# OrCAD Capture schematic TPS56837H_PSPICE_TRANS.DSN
size C
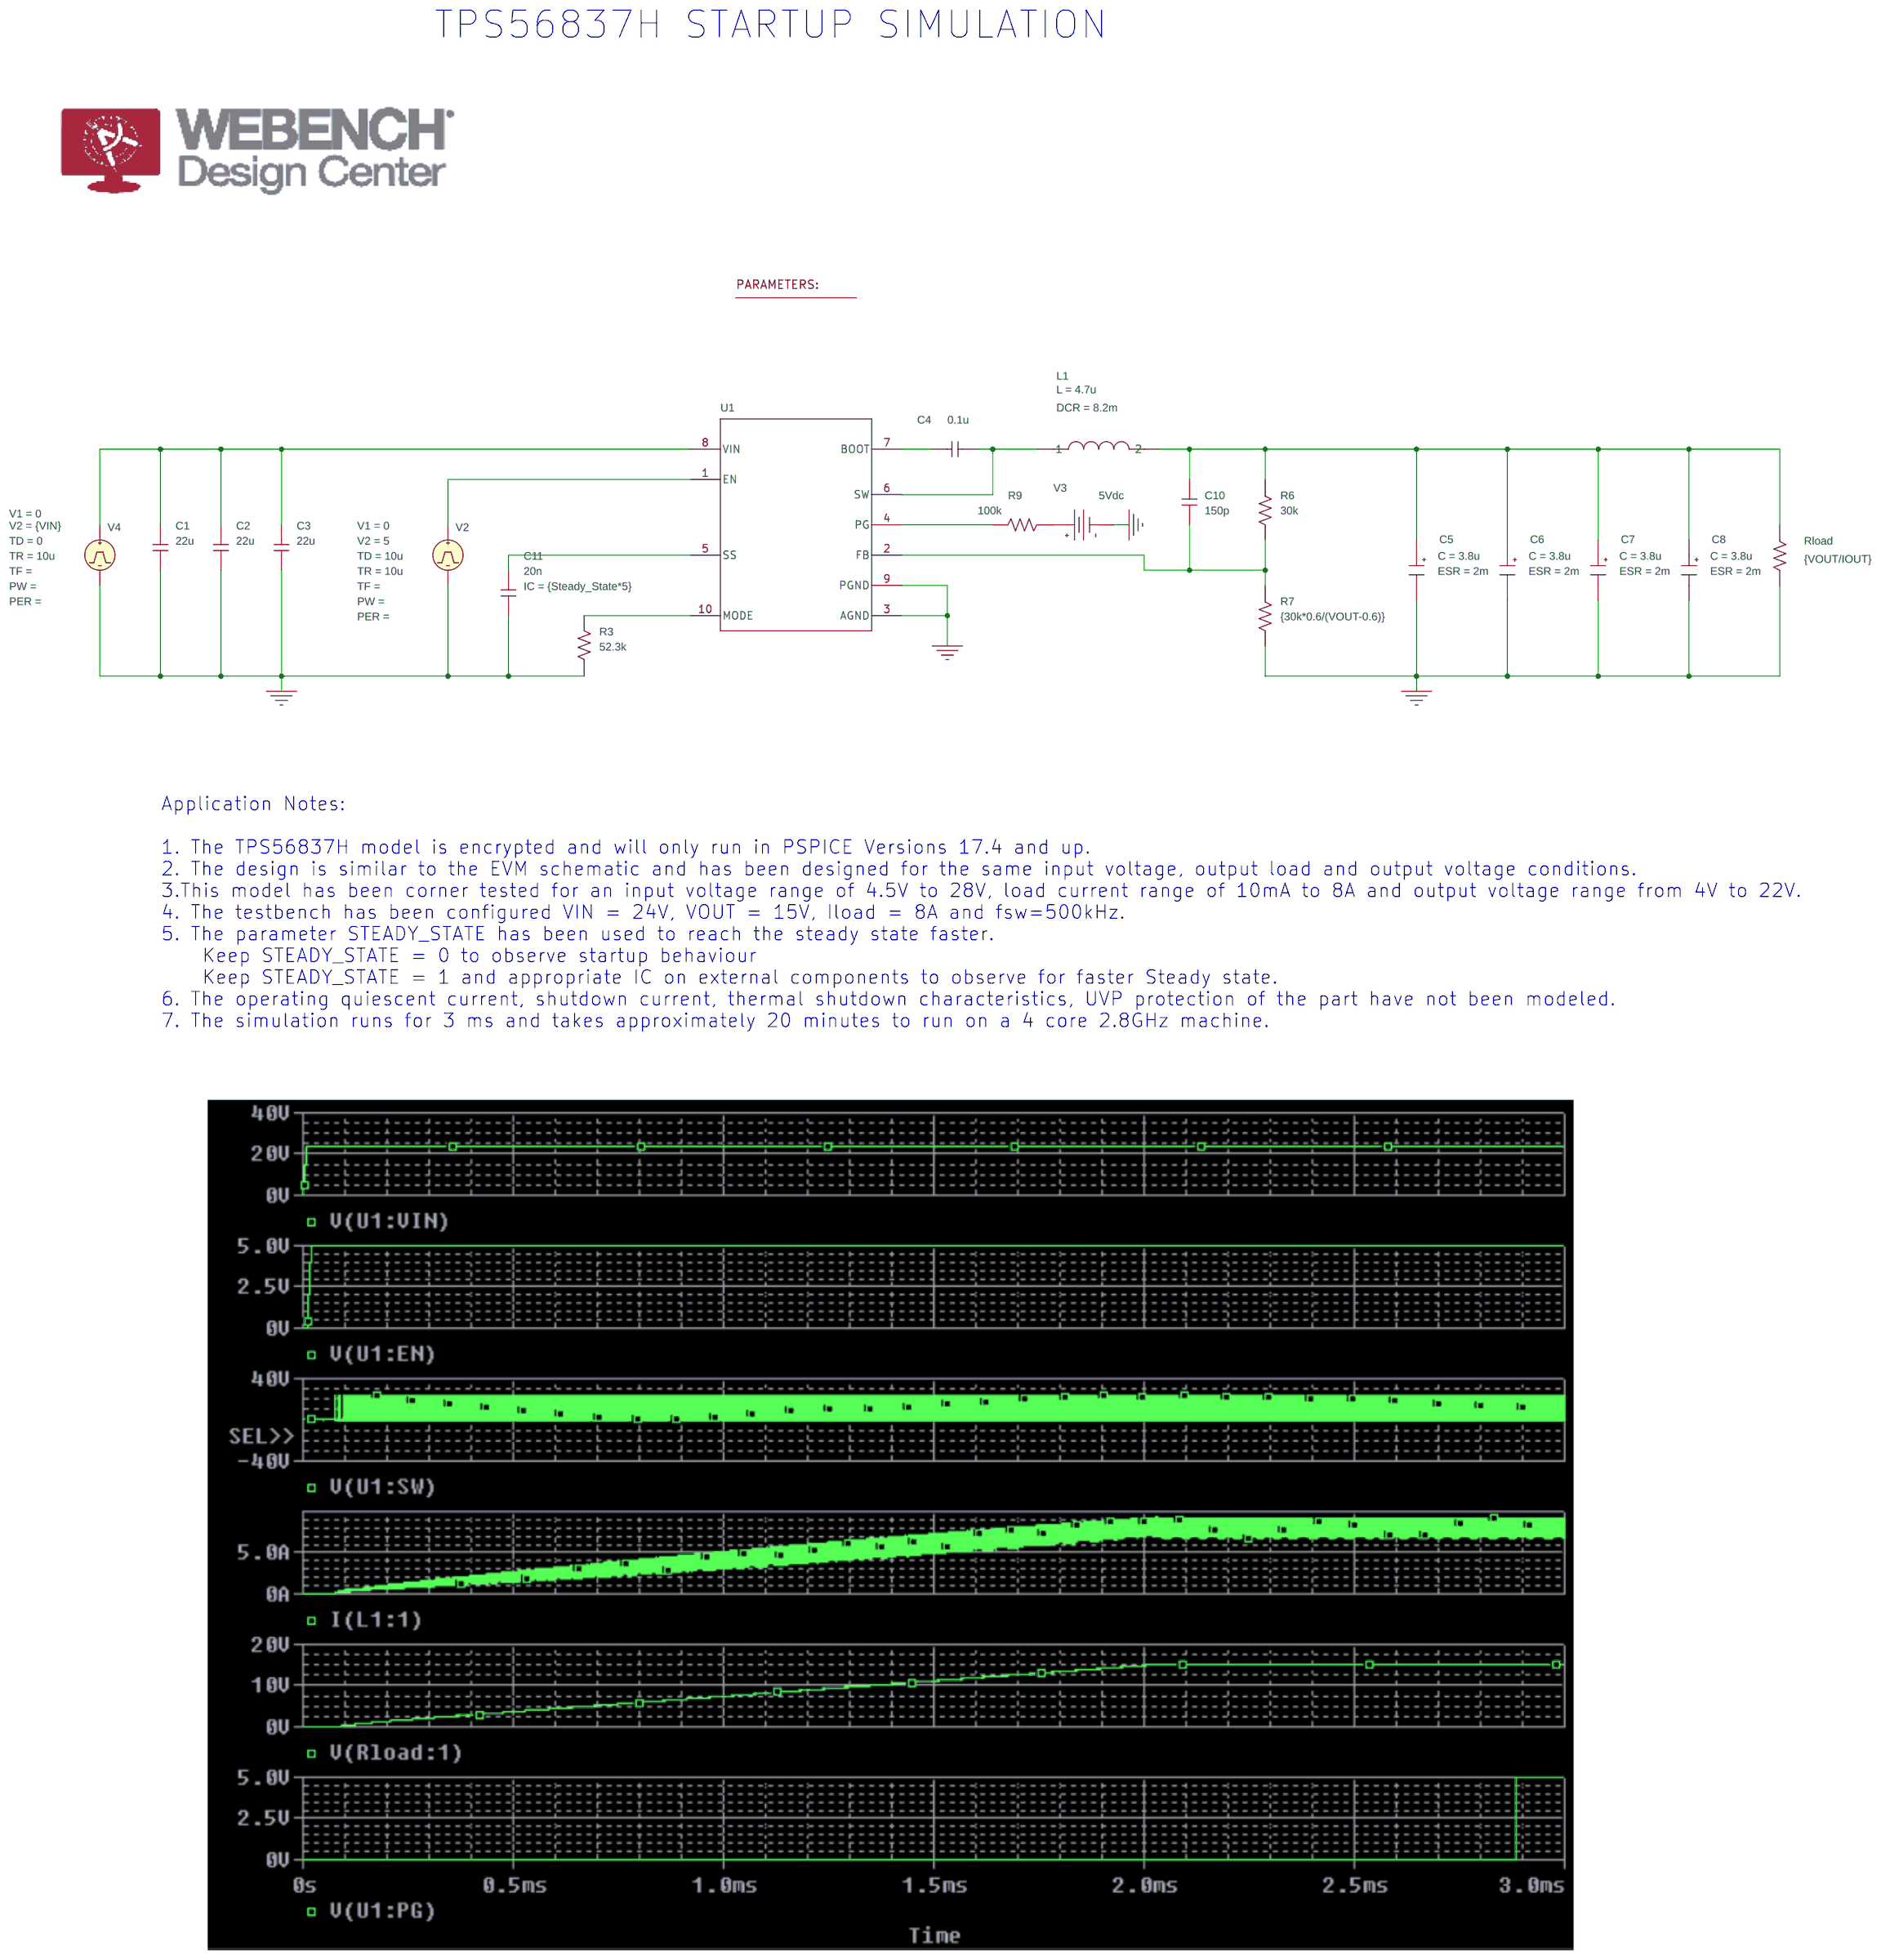
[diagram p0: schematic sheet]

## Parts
3  PARAM
C1  22u  [cap196]
C2  22u  [cap196]
C3  22u  [cap196]
C4  0.1u  [cap196]
C5  CESR
C6  CESR
C7  CESR
C8  CESR
C10  150p  [cap196]
C11  20n  [RAD/CK05]
L1  LDCR
R3  52.3k  [AXRC05]
R6  30k  [AX/RC05]
R7  {30k*0.6/(VOUT-0.6)}  [AX/RC05]
R9  100k  [AXRC05]
Rload  {VOUT/IOUT}  [AX/RC05]
U1  Value  [RPA0010A-MFG]
V2  VPULSE
V3  VDC
V4  VPULSE

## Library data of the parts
3 = PARAM: IOUT: 8; Steady_State: 0; VIN: 24; VOUT: 15
C1-C3 C10 = C: IC: 0
C4 = C: IC: 0; VC1: 5
C5-C8 = CESR_0: C: 3.8u; ESL: 0; ESR: 2m; IC: 0
C11 = C: IC: {Steady_State*5}
L1 = LDCR: DCR: 8.2m; IC: 0; L: 4.7u
R3 R6 R7 R9 Rload = R
U1 = TPS56837HRPA_TRANS
V2 = VPULSE: TD: 10u; TR: 10u; V1: 0; V2: 5
V3 = VDC: DC: 5Vdc
V4 = VPULSE: TD: 0; TR: 10u; V1: 0; V2: {VIN}

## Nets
0: C1.1 C2.1 C3.1 C5.2(OUT) C6.2(OUT) C7.2(OUT) C8.2(OUT) C11.2 R3.1 R7.2 Rload.2 U1.3(AGND) U1.9(PGND) V2.2(-) V3.1(-) V4.2(-)
N95703: C1.2 C2.2 C3.2 U1.8(VIN) V4.1(+)
N95737: C4.2 U1.7(BOOT)
N95743: C4.1 L1.1 U1.6(SW)
N95759: C5.1(IN) C6.1(IN) C7.1(IN) C8.1(IN) C10.2 L1.2 R6.1 Rload.1
N95825: U1.1(EN) V2.1(+)
N95931: R9.2 U1.4(PG)
N95943: C10.1 R6.2 R7.1 U1.2(FB)
N96113: C11.1 U1.5(SS)
N96363: R3.2 U1.10(MODE)
N106965: R9.1 V3.0(+)

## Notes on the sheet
- TPS56837H STARTUP SIMULATION
- Application Notes:
  1. The TPS56837H model is encrypted and will only run in PSPICE Versions 17.4 and up.
  2. The design is similar to the EVM schematic and has been designed for the same input voltage, output load and output voltage conditions.
  3.This model has been corner tested for an input voltage range of 4.5V to 28V, load current range of 10mA to 8A and output voltage range from 4V to 22V.
  4. The testbench has been configured VIN = 24V, VOUT = 15V, Iload = 8A and fsw=500kHz.
  5. The parameter STEADY_STATE has been used to reach the steady state faster.
      Keep STEADY_STATE = 0 to observe startup behaviour
      Keep STEADY_STATE = 1 and appropriate IC on external components to observe for faster Steady state.
  6. The operating quiescent current, shutdown current, thermal shutdown characteristics, UVP protection of the part have not been modeled.
  7. The simulation runs for 3 ms and takes approximately 20 minutes to run on a 4 core 2.8GHz machine.
